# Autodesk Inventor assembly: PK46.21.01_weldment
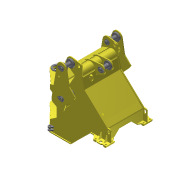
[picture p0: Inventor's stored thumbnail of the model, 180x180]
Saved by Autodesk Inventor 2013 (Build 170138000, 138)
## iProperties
Created: 2005-04
Part Number: PK46.21.01_weldment
Document SubType Name: Assembly
Designer: salex
Manufacturer: Standard
Standards Organization: Custom
Author: salex
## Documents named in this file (31)
- C:\Product Design Suite 2013\Data\Assy, Chassis, Front\PK46.21.01_weldment.iam
- C:\Product Design Suite 2013\Data\Assy, Chassis, Front\PK46.21.01.010.iam
- C:\Product Design Suite 2013\Data\Assy, Chassis, Front\PK46.21.01.020.iam
- C:\Product Design Suite 2013\Data\Assy, Chassis, Front\PK46.21.01.030.iam
- C:\Product Design Suite 2013\Data\Assy, Chassis, Front\PK46.21.01.040.iam
- C:\Product Design Suite 2013\Data\Assy, Chassis, Front\PK46.21.01.050.iam
- C:\Product Design Suite 2013\Data\Assy, Chassis, Front\PK46.21.01.060.iam
- C:\Product Design Suite 2013\Data\Assy, Chassis, Front\PK46.21.01.070.iam
- C:\Product Design Suite 2013\Data\Assy, Chassis, Front\PK46.21.01.025.ipt
- C:\Product Design Suite 2013\Data\Assy, Chassis, Front\PK46.21.01.026.ipt
- C:\Product Design Suite 2013\Data\Assy, Chassis, Front\PK46.21.01.027.ipt
- C:\Product Design Suite 2013\Data\Assy, Chassis, Front\PK46.21.01.028.ipt
- C:\Product Design Suite 2013\Data\Assy, Chassis, Front\PK46.21.01.029.ipt
- C:\Product Design Suite 2013\Data\Assy, Chassis, Front\PK46.21.01.031.ipt
- C:\Product Design Suite 2013\Data\Assy, Chassis, Front\027.32.02.621.ipt
- C:\Product Design Suite 2013\Data\Assy, Chassis, Front\PK46.21.01.035.ipt
- C:\Product Design Suite 2013\Data\Assy, Chassis, Front\PK46.21.01.036.ipt
- C:\Product Design Suite 2013\Data\Assy, Chassis, Front\PK46.21.01.032_1.ipt
- C:\Product Design Suite 2013\Data\Assy, Chassis, Front\_PK46.21.01.080.iam
- C:\Product Design Suite 2013\Data\Assy, Chassis, Front\027.13.14.227.ipt
- C:\Product Design Suite 2013\Data\Assy, Chassis, Front\027.13.12.227.ipt
- C:\Product Design Suite 2013\Data\Assy, Chassis, Front\Part 3.ipt
- C:\Product Design Suite 2013\Data\Assy, Chassis, Front\Flap.ipt
- C:\Product Design Suite 2013\Data\Assy, Chassis, Front\PK46.25.00.020.iam
- C:\Product Design Suite 2013\Data\Assy, Chassis, Front\PK46.25.00.006.ipt
- C:\Product Design Suite 2013\Data\Assy, Chassis, Front\PK46.25.00.008.ipt
- C:\Product Design Suite 2013\Data\Assy, Chassis, Front\PK46.25.00.007.ipt
- C:\Product Design Suite 2013\Data\Assy, Chassis, Front\PK46.25.00.010.iam
- C:\Product Design Suite 2013\Data\Assy, Chassis, Front\PK46.25.00.005.ipt
- Part 3.ipt
- Flap.ipt
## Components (57 placed, 28 different names)
1. PK46.21.01.010:1 [sub-assembly] — Mate:1, Mate:3, Mate:6, Mate:9, Angle:1, Mate:10, Flush:3, Angle:4, Mate:17, Mate:18, Mate:19, Mate:33, Mate:34, Mate:45, Mate:54, Mate:61, Mate:67, Mate:68, Mate:73, Angle:8
2. PK46.21.01.020:1 [sub-assembly] — Mate:2, Mate:4, Mate:6, Mate:8, Mate:39, Mate:40, Mate:59, Mate:66, Mate:69, Mate:72, Angle:7, Flush:16, Mate:100
3. PK46.21.01.030:1 [sub-assembly] — Mate:17, Mate:23, Mate:24, Mate:25, Tangent:1, Tangent:2, Tangent:3
4. PK46.21.01.040:1 [sub-assembly] — Mate:3, Mate:4, Mate:7, Flush:2, Mate:13, Angle:2, Angle:5
5. PK46.21.01.050:1 [sub-assembly] — Mate:1, Mate:2, Mate:7, Flush:2, Angle:4, Angle:6, Mate:55, Mate:64, Mate:65, Mate:70, Mate:71
6. PK46.21.01.060:1 [sub-assembly] — Mate:9, Flush:1, Angle:1, Mate:10, Mate:11, Flush:3, Mate:16, Mate:35, Mate:36, Mate:37, Mate:38, Mate:46, Mate:50, Mate:56, Flush:5, Mate:47, Mate:75
7. PK46.21.01.070:1 [sub-assembly] — Mate:8, Flush:1, Mate:11, Mate:41, Mate:42, Mate:43, Mate:44, Mate:49, Mate:53, Mate:57, Flush:6
8. _PK46.21.01.080:1 [sub-assembly] — Mate:32, Mate:54, Mate:55
9. Flap:1
10. PK46.25.00.020:4 [sub-assembly]
11. PK46.25.00.006:5
12. PK46.25.00.006:8
13. PK46.25.00.008:4
14. PK46.25.00.007:4
15. PK46.25.00.010:1 [sub-assembly]
16. PK46.25.00.005:1
17. PK46.25.00.007:2
18. PK46.25.00.008:2
19. PK46.25.00.006:4
20. PK46.25.00.006:3
21. PK46.25.00.020:1 [sub-assembly]
22. 027.13.14.227:4
23. 027.13.12.227:3
24. Part 3:1
25. Part 3:2
26. PK46.25.00.020:3 [sub-assembly]
27. PK46.25.00.020:2 [sub-assembly]
28. PK46.25.00.006:2
29. PK46.25.00.008:1
30. PK46.25.00.007:1
31. PK46.25.00.008:3
32. PK46.25.00.007:3
33. PK46.25.00.006:7
34. PK46.25.00.005:2
35. PK46.25.00.008:5
36. PK46.25.00.007:5
37. PK46.25.00.006:1
38. PK46.25.00.006:6
39. 027.13.14.227:8
40. 027.13.12.227:8
41. PK46.21.01.032_1:1
42. PK46.21.01.032_1:2
43. PK46.21.01.025:1 — Mate:45, Mate:46, Flush:4, Mate:47, Mate:48, Mate:74
44. PK46.21.01.026:1 — Mate:52, Mate:53, Mate:58, Mate:60, Flush:4
45. PK46.21.01.027:1 — Mate:49, Mate:50, Mate:51, Mate:52, Mate:48
46. PK46.21.01.028:1 — Mate:56, Mate:58, Mate:61
47. PK46.21.01.028:2 — Mate:57, Mate:59, Mate:60
48. PK46.21.01.029:1 — Mate:64, Mate:67
49. PK46.21.01.029:2 — Mate:65, Mate:66
50. PK46.21.01.031:1 — Mate:68, Flush:5, Mate:70
51. PK46.21.01.031:2 — Mate:69, Flush:6, Mate:71
52. 027.32.02.621:1 — Mate:33, Mate:36, Mate:37
53. 027.32.02.621:2 — Mate:34, Mate:35, Mate:38
54. 027.32.02.621:3 — Mate:40, Mate:41, Mate:44
55. 027.32.02.621:4 — Mate:39, Mate:42, Mate:43
56. PK46.21.01.036:1 — Mate:72, Tangent:1, Tangent:2, Angle:7
57. PK46.21.01.035:1 — Mate:73, Mate:74, Angle:8, Tangent:3, Mate:76
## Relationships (79: Mate 62, Flush 7, Angle 7, Tangent 3)
- Mate:1: PK46.21.01.010:1 ↔ PK46.21.01.050:1
- Mate:2: PK46.21.01.020:1 ↔ PK46.21.01.050:1
- Mate:3: PK46.21.01.010:1 ↔ PK46.21.01.040:1
- Mate:4: PK46.21.01.020:1 ↔ PK46.21.01.040:1
- Mate:6: PK46.21.01.010:1 ↔ PK46.21.01.020:1
- Mate:7: PK46.21.01.040:1 ↔ PK46.21.01.050:1
- Mate:8: PK46.21.01.020:1 ↔ PK46.21.01.070:1
- Mate:9: PK46.21.01.010:1 ↔ PK46.21.01.060:1
- Flush:1: PK46.21.01.060:1 ↔ PK46.21.01.070:1
- Angle:1: PK46.21.01.010:1 ↔ PK46.21.01.060:1
- Mate:10: PK46.21.01.010:1 ↔ PK46.21.01.060:1
- Mate:11: PK46.21.01.060:1 ↔ PK46.21.01.070:1
- Flush:2: PK46.21.01.040:1 ↔ PK46.21.01.050:1
- Flush:3: PK46.21.01.010:1 ↔ PK46.21.01.060:1
- Mate:13: PK46.21.01.040:1
- Angle:2: PK46.21.01.040:1
- Angle:4: PK46.21.01.010:1 ↔ PK46.21.01.050:1
- Angle:5: PK46.21.01.040:1
- Mate:16: PK46.21.01.060:1
- Mate:17: PK46.21.01.010:1 ↔ PK46.21.01.030:1
- Mate:18: PK46.21.01.010:1
- Mate:19: PK46.21.01.010:1
- Angle:6: PK46.21.01.050:1
- Mate:23: PK46.21.01.030:1
- Mate:24: PK46.21.01.030:1
- Mate:25: PK46.21.01.030:1
- Mate:32: _PK46.21.01.080:1
- Mate:33: PK46.21.01.010:1 ↔ 027.32.02.621:1
- Mate:34: PK46.21.01.010:1 ↔ 027.32.02.621:2
- Mate:35: PK46.21.01.060:1 ↔ 027.32.02.621:2
- Mate:36: PK46.21.01.060:1 ↔ 027.32.02.621:1
- Mate:37: PK46.21.01.060:1 ↔ 027.32.02.621:1
- Mate:38: PK46.21.01.060:1 ↔ 027.32.02.621:2
- Mate:39: PK46.21.01.020:1 ↔ 027.32.02.621:4
- Mate:40: PK46.21.01.020:1 ↔ 027.32.02.621:3
- Mate:41: PK46.21.01.070:1 ↔ 027.32.02.621:3
- Mate:42: PK46.21.01.070:1 ↔ 027.32.02.621:4
- Mate:43: PK46.21.01.070:1 ↔ 027.32.02.621:4
- Mate:44: PK46.21.01.070:1 ↔ 027.32.02.621:3
- Mate:45: PK46.21.01.010:1 ↔ PK46.21.01.025:1
- Mate:46: PK46.21.01.060:1 ↔ PK46.21.01.025:1
- Mate:49: PK46.21.01.070:1 ↔ PK46.21.01.027:1
- Mate:50: PK46.21.01.060:1 ↔ PK46.21.01.027:1
- Mate:51: PK46.21.01.027:1
- Mate:52: PK46.21.01.026:1 ↔ PK46.21.01.027:1
- Mate:53: PK46.21.01.070:1 ↔ PK46.21.01.026:1
- Mate:54: PK46.21.01.010:1 ↔ _PK46.21.01.080:1
- Mate:55: PK46.21.01.050:1 ↔ _PK46.21.01.080:1
- Mate:56: PK46.21.01.060:1 ↔ PK46.21.01.028:1
- Mate:57: PK46.21.01.070:1 ↔ PK46.21.01.028:2
- Mate:58: PK46.21.01.026:1 ↔ PK46.21.01.028:1
- Mate:59: PK46.21.01.020:1 ↔ PK46.21.01.028:2
- Mate:60: PK46.21.01.026:1 ↔ PK46.21.01.028:2
- Mate:61: PK46.21.01.010:1 ↔ PK46.21.01.028:1
- Mate:64: PK46.21.01.050:1 ↔ PK46.21.01.029:1
- Mate:65: PK46.21.01.050:1 ↔ PK46.21.01.029:2
- Mate:66: PK46.21.01.020:1 ↔ PK46.21.01.029:2
- Mate:67: PK46.21.01.010:1 ↔ PK46.21.01.029:1
- Mate:68: PK46.21.01.010:1 ↔ PK46.21.01.031:1
- Mate:69: PK46.21.01.020:1 ↔ PK46.21.01.031:2
- Flush:5: PK46.21.01.060:1 ↔ PK46.21.01.031:1
- Flush:6: PK46.21.01.070:1 ↔ PK46.21.01.031:2
- Mate:70: PK46.21.01.050:1 ↔ PK46.21.01.031:1
- Mate:71: PK46.21.01.050:1 ↔ PK46.21.01.031:2
- Flush:4: PK46.21.01.025:1 ↔ PK46.21.01.026:1
- Mate:47: PK46.21.01.060:1 ↔ PK46.21.01.025:1
- Mate:48: PK46.21.01.025:1 ↔ PK46.21.01.027:1
- Mate:72: PK46.21.01.020:1 ↔ PK46.21.01.036:1
- Tangent:1: PK46.21.01.030:1 ↔ PK46.21.01.036:1
- Tangent:2: PK46.21.01.030:1 ↔ PK46.21.01.036:1
- Angle:7: PK46.21.01.020:1 ↔ PK46.21.01.036:1
- Mate:73: PK46.21.01.010:1 ↔ PK46.21.01.035:1
- Mate:74: PK46.21.01.025:1 ↔ PK46.21.01.035:1
- Angle:8: PK46.21.01.010:1 ↔ PK46.21.01.035:1
- Tangent:3: PK46.21.01.030:1 ↔ PK46.21.01.035:1
- Mate:75: PK46.21.01.060:1
- Mate:76: PK46.21.01.035:1
- Flush:16: PK46.21.01.020:1
- Mate:100: PK46.21.01.020:1
## Named parameters: d389_d402 = 0, d390_d403 = 0, d391_d404 = 0, d392_d405 = 0, d393_d406 = 0, d394_d407 = 0, d395_d408 = 0, d396_d409 = 0, d397_d410 = 0, d398_d411 = 0, d399_d412 = 0, d400_d413 = 0, d401_d415 = 0, d402_d416 = 0, d403_d417 = 0, d404_d418 = 0, d405_d419 = 0, d406_d420 = 0, d407_d421 = 0, d408_d422 = 0, d409_d423 = 0, d410_d424 = 0, d411_d425 = 0, d432_d159 = 0
